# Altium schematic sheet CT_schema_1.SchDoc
size 539 x 541 mm
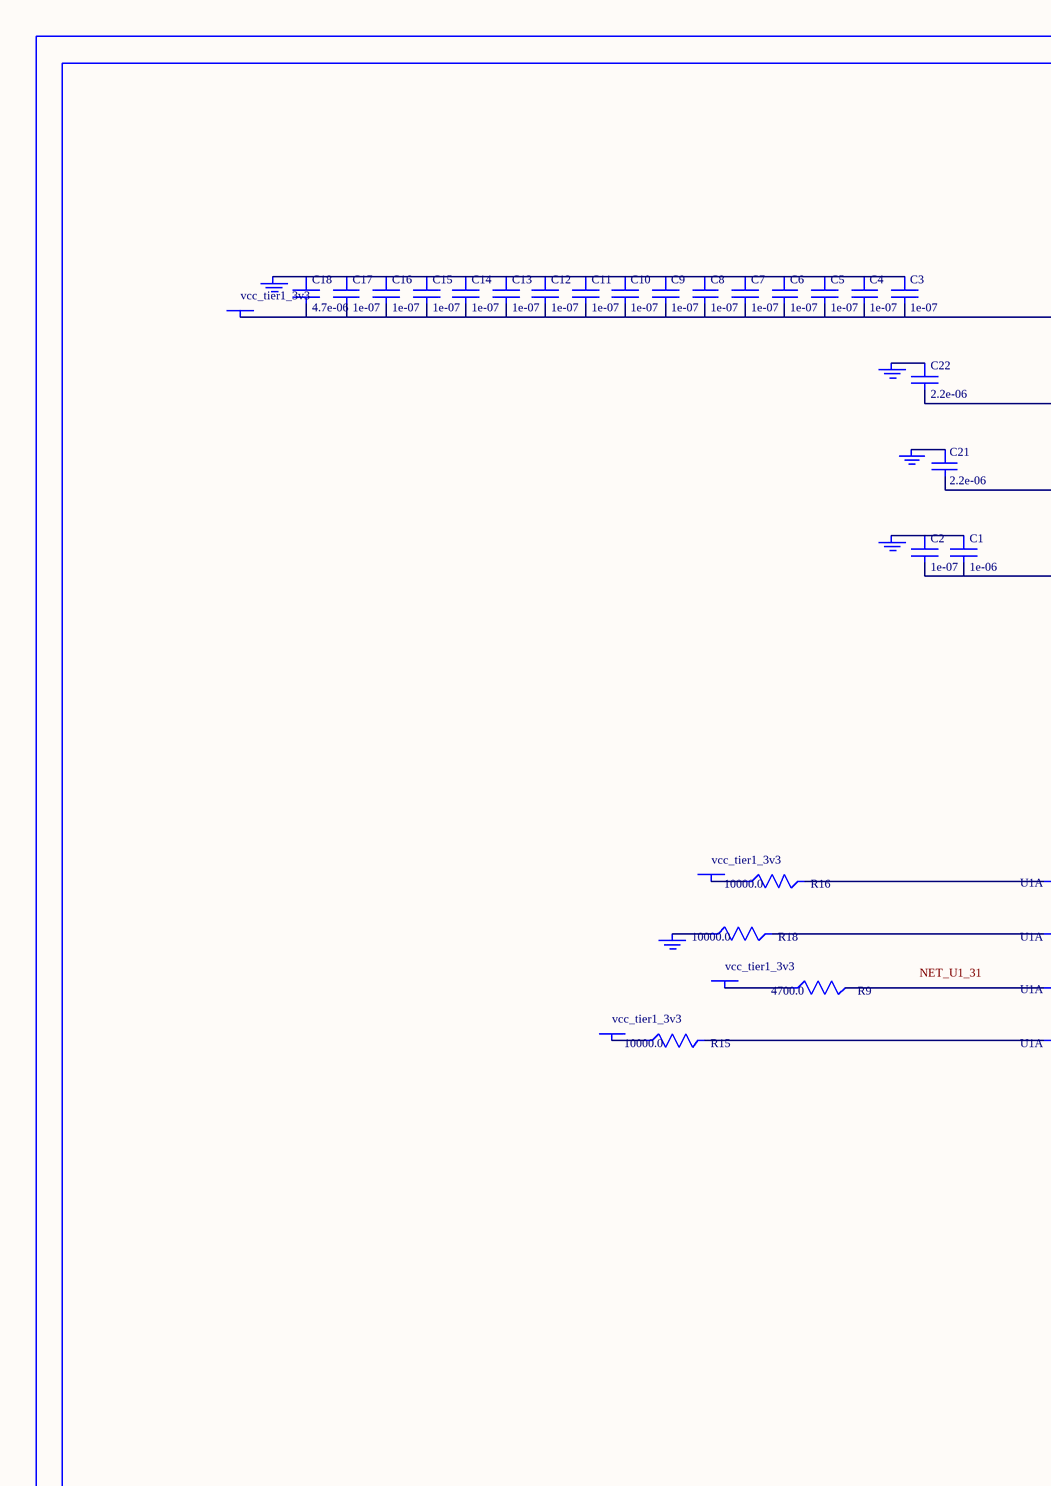
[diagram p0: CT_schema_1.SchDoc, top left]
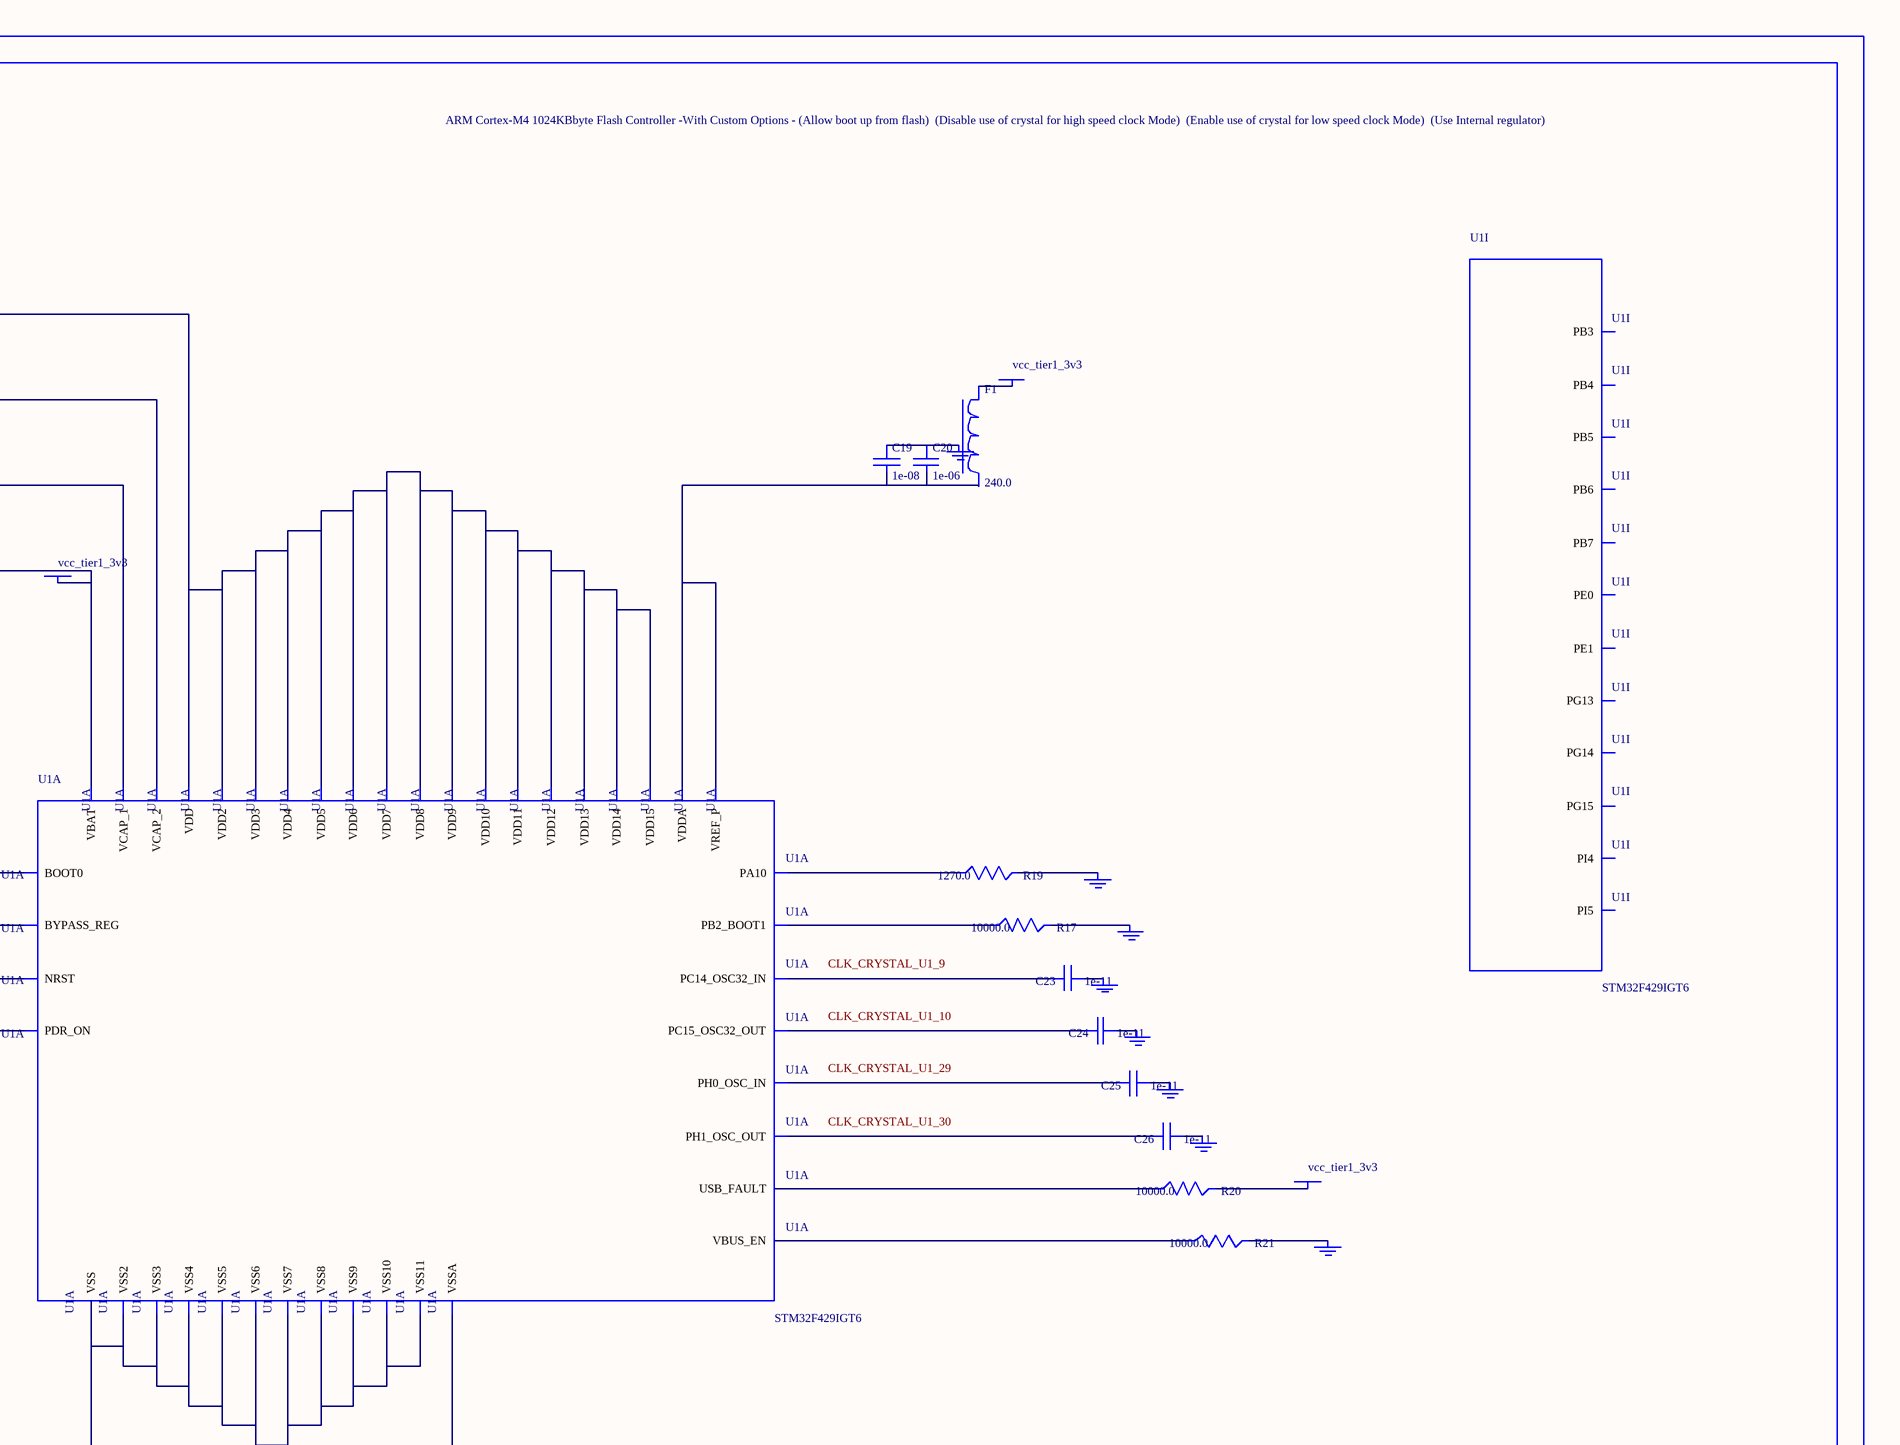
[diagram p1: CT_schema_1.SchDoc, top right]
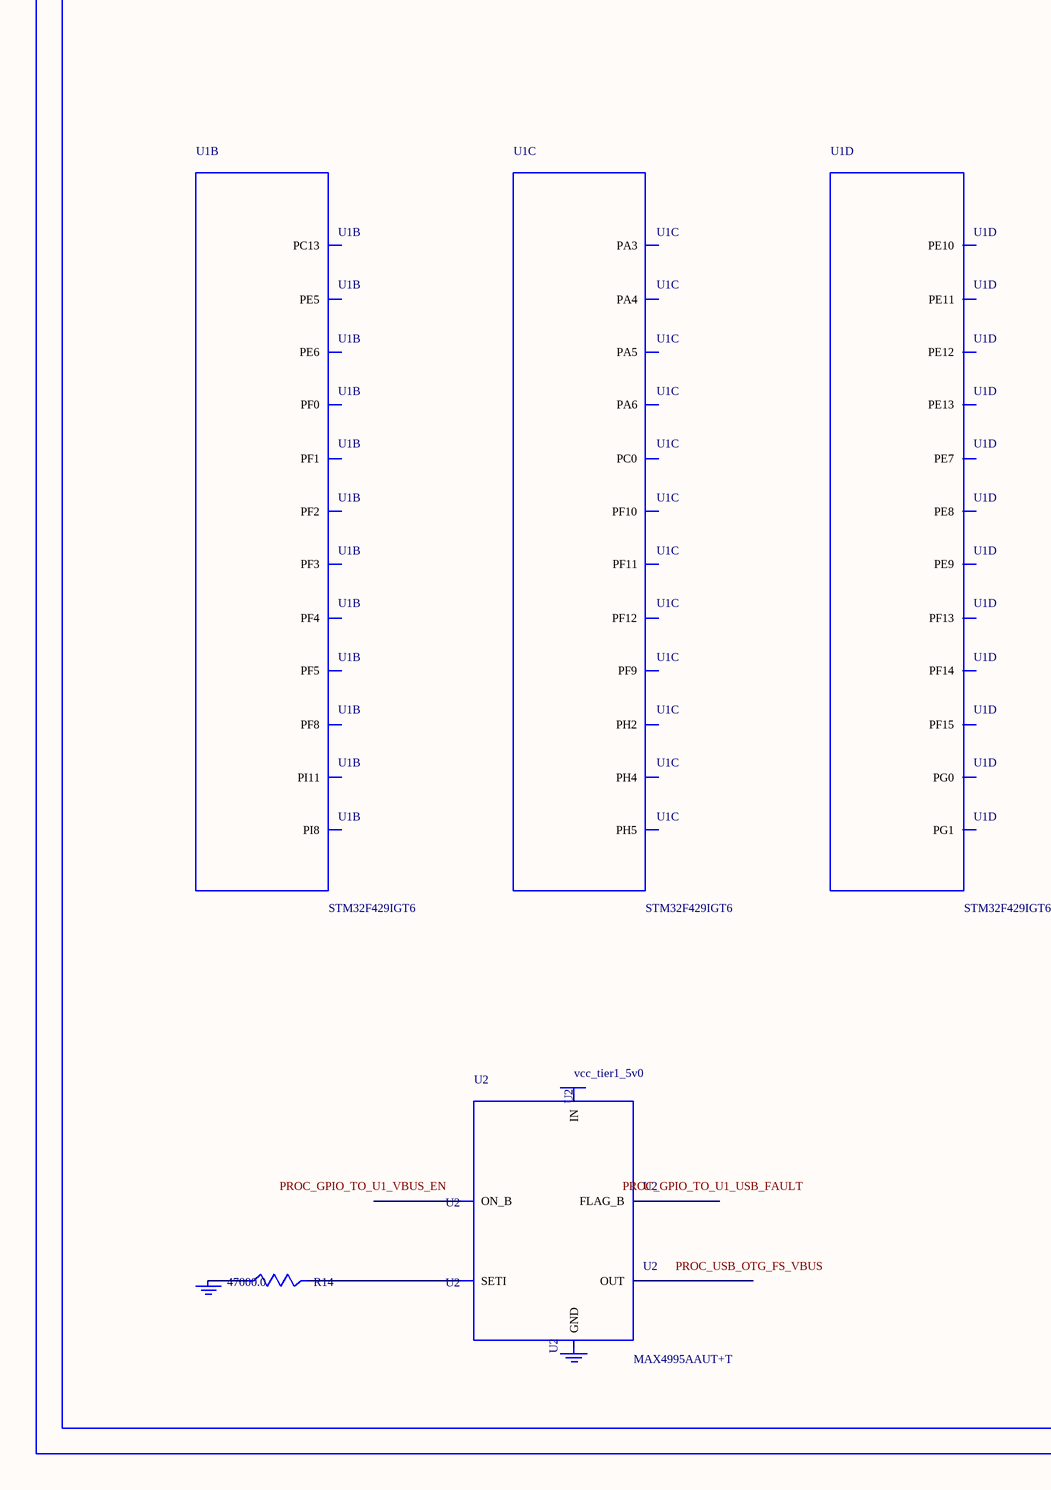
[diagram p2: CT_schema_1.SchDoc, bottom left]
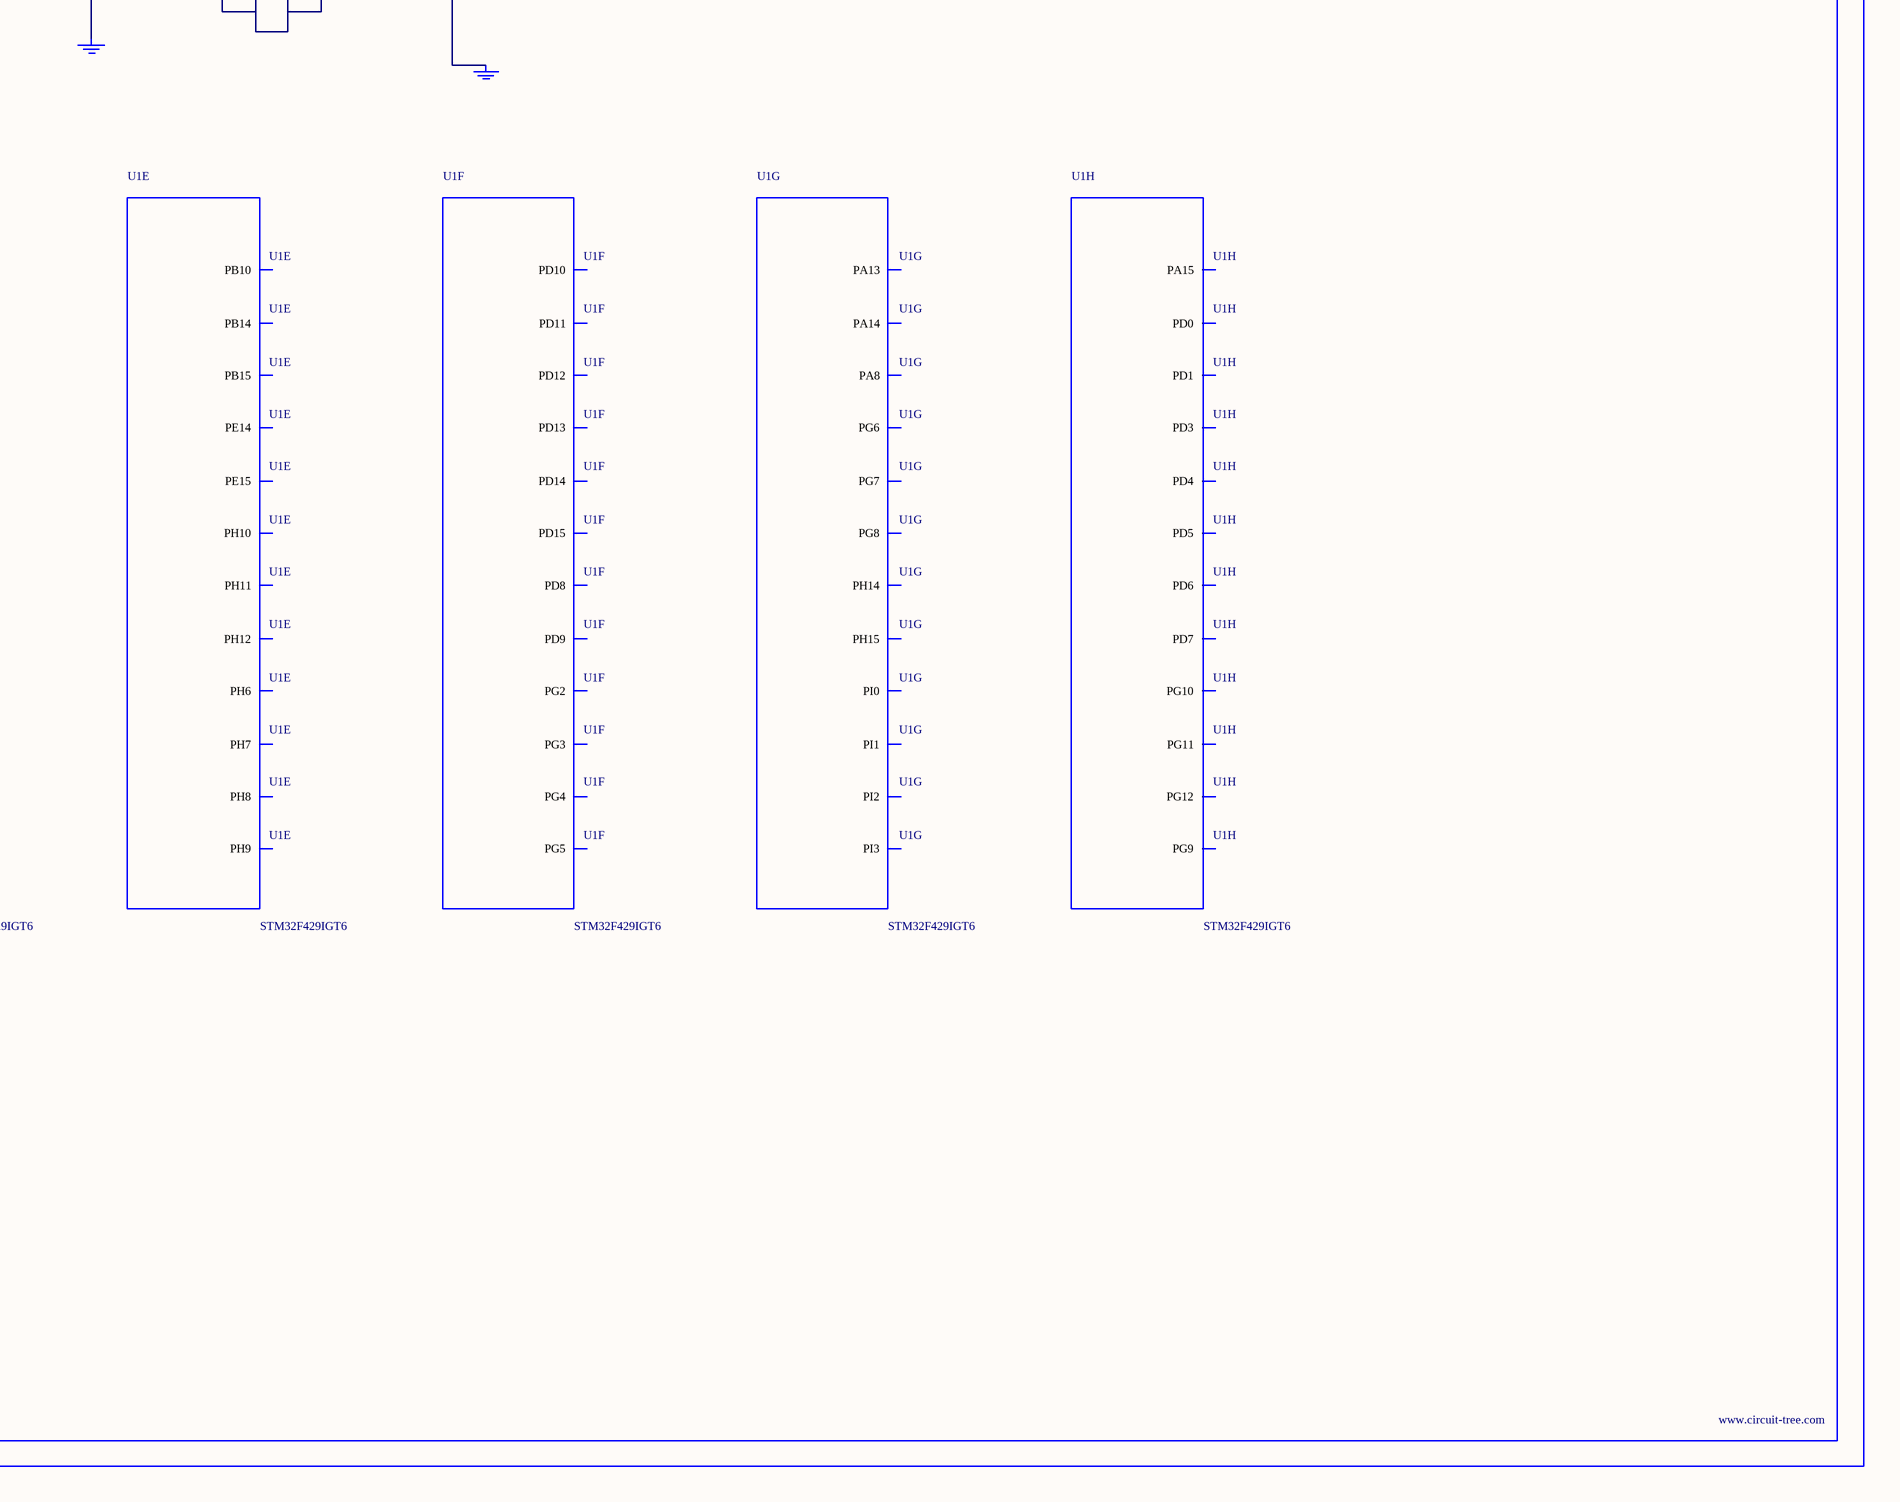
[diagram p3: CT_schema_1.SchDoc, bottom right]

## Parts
BORDER0  (no value)
C1  1e-06  [C0603]
C2  1e-07  [C0603]
C3  1e-07  [C0603]
C4  1e-07  [C0603]
C5  1e-07  [C0603]
C6  1e-07  [C0603]
C7  1e-07  [C0603]
C8  1e-07  [C0603]
C9  1e-07  [C0603]
C10  1e-07  [C0603]
C11  1e-07  [C0603]
C12  1e-07  [C0603]
C13  1e-07  [C0603]
C14  1e-07  [C0603]
C15  1e-07  [C0603]
C16  1e-07  [C0603]
C17  1e-07  [C0603]
C18  4.7e-06  [C0603]
C19  1e-08  [C0603]
C20  1e-06  [C0603]
C21  2.2e-06  [C0603]
C22  2.2e-06  [C0603]
C23  1e-11  [C0402]
C24  1e-11  [C0402]
C25  1e-11  [C0402]
C26  1e-11  [C0402]
F1  240.0  [L0603]
GND_INSTANCE_0_0  (no value)
GND_INSTANCE_0_1  (no value)
GND_INSTANCE_0_2  (no value)
GND_INSTANCE_0_3  (no value)
GND_INSTANCE_0_4  (no value)
GND_INSTANCE_0_5  (no value)
GND_INSTANCE_0_6  (no value)
GND_INSTANCE_0_7  (no value)
GND_INSTANCE_0_8  (no value)
GND_INSTANCE_0_9  (no value)
GND_INSTANCE_0_10  (no value)
GND_INSTANCE_0_11  (no value)
GND_INSTANCE_0_12  (no value)
GND_INSTANCE_0_13  (no value)
GND_INSTANCE_0_14  (no value)
GND_INSTANCE_0_15  (no value)
GND_INSTANCE_0_16  (no value)
POWER_INSTANCE_0_0  vcc_tier1_3v3
POWER_INSTANCE_0_1  vcc_tier1_3v3
POWER_INSTANCE_0_2  vcc_tier1_3v3
POWER_INSTANCE_0_3  vcc_tier1_3v3
POWER_INSTANCE_0_4  vcc_tier1_3v3
POWER_INSTANCE_0_5  vcc_tier1_3v3
POWER_INSTANCE_0_6  vcc_tier1_3v3
POWER_INSTANCE_0_7  vcc_tier1_5v0
R9  4700.0  [R0603]
R14  47000.0  [R0603]
R15  10000.0  [R0603]
R16  10000.0  [R0603]
R17  10000.0  [R0603]
R18  10000.0  [R0603]
R19  1270.0  [R0603]
R20  10000.0  [R0603]
R21  10000.0  [R0603]
U1  STM32F429IGT6  [LQFP176]  (parts A,B,C,D,E,F,G,H,I of 15)
U2  MAX4995AAUT+T  [SOT-23-6]

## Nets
NetC1_1: C1.1 C2.1 GND_INSTANCE_0_1.0(GND)
NetC1_2: C1.2 C2.2 POWER_INSTANCE_0_1.0(PWR) U1.6(VBAT)
NetC3_1: C3.1 C4.1 C5.1 C6.1 C7.1 C8.1 C9.1 C10.1 C11.1 C12.1 C13.1 C14.1 C15.1 C16.1 C17.1 C18.1 GND_INSTANCE_0_4.0(GND)
NetC3_2: C3.2 C4.2 C5.2 C6.2 C7.2 C8.2 C9.2 C10.2 C11.2 C12.2 C13.2 C14.2 C15.2 C16.2 C17.2 C18.2 POWER_INSTANCE_0_2.0(PWR) U1.15(VDD) U1.23(VDD2) U1.36(VDD3) U1.49(VDD4) U1.62(VDD5) U1.72(VDD6) U1.82(VDD7) U1.91(VDD8) U1.103(VDD9) U1.114(VDD10) U1.127(VDD11) U1.136(VDD12) U1.149(VDD13) U1.159(VDD14) U1.172(VDD15)
NetC19_1: C19.1 C20.1 GND_INSTANCE_0_8.0(GND)
NetC19_2: C19.2 C20.2 U1.38(VREF_P) U1.39(VDDA)
NetC21_1: C21.1 GND_INSTANCE_0_11.0(GND)
NetC21_2: C21.2 U1.81(VCAP_1)
NetC22_1: C22.1 GND_INSTANCE_0_13.0(GND)
NetC22_2: C22.2 U1.125(VCAP_2)
NetC23_1: C23.1 GND_INSTANCE_0_2.0(GND)
NetC23_2: C23.2 U1.9(PC14_OSC32_IN)
NetC24_1: C24.1 GND_INSTANCE_0_3.0(GND)
NetC24_2: C24.2 U1.10(PC15_OSC32_OUT)
NetC25_1: C25.1 GND_INSTANCE_0_5.0(GND)
NetC25_2: C25.2 U1.29(PH0_OSC_IN)
NetC26_1: C26.1 GND_INSTANCE_0_6.0(GND)
NetC26_2: C26.2 U1.30(PH1_OSC_OUT)
NetF1_1: F1.1 POWER_INSTANCE_0_3.0(PWR)
NetGND_INSTANCE_0_0_0: GND_INSTANCE_0_0.0(GND) R21.2
NetGND_INSTANCE_0_7_0: GND_INSTANCE_0_7.0(GND) U1.37(VSSA)
NetGND_INSTANCE_0_9_0: GND_INSTANCE_0_9.0(GND) R18.1
NetGND_INSTANCE_0_10_0: GND_INSTANCE_0_10.0(GND) R17.2
NetGND_INSTANCE_0_12_0: GND_INSTANCE_0_12.0(GND) R19.2
NetGND_INSTANCE_0_14_0: GND_INSTANCE_0_14.0(GND) U1.14(VSS) U1.22(VSS2) U1.61(VSS3) U1.71(VSS4) U1.90(VSS5) U1.102(VSS6) U1.113(VSS7) U1.126(VSS8) U1.135(VSS9) U1.148(VSS10) U1.158(VSS11)
NetGND_INSTANCE_0_15_0: GND_INSTANCE_0_15.0(GND) R14.1
NetPOWER_INSTANCE_0_0_0: POWER_INSTANCE_0_0.0(PWR) R20.2
NetPOWER_INSTANCE_0_4_0: POWER_INSTANCE_0_4.0(PWR) R16.1
NetPOWER_INSTANCE_0_5_0: POWER_INSTANCE_0_5.0(PWR) R15.1
NetPOWER_INSTANCE_0_6_0: POWER_INSTANCE_0_6.0(PWR) R9.1
NetR9_2: R9.2 U1.31(NRST)
NetR14_2: R14.2 U2.3(SETI)
NetR15_2: R15.2 U1.171(PDR_ON)
NetR16_2: R16.2 U1.166(BOOT0)
NetR17_1: R17.1 U1.58(PB2_BOOT1)
NetR18_2: R18.2 U1.48(BYPASS_REG)
NetR19_1: R19.1 U1.121(PA10)
NetR20_1: R20.1 U1.3(USB_FAULT)
NetR21_1: R21.1 U1.2(VBUS_EN)

Not connected (* = marked no-connect by the designer): F1 2; GND_INSTANCE_0_16 0(GND); POWER_INSTANCE_0_7 0(PWR); U1 4(PE5) 5(PE6) 7(PI8) 8(PC13) 13(PI11) 16(PF0) 17(PF1) 18(PF2) 19(PF3) 20(PF4) 21(PF5) 26(PF8) 27(PF9) 28(PF10) 32(PC0) 43(PH2) 45(PH4) 46(PH5) 47(PA3) 50(PA4) 51(PA5) 52(PA6) 59(PF11) 60(PF12) 63(PF13) 64(PF14) 65(PF15) 66(PG0) 67(PG1) 68(PE7) 69(PE8) 70(PE9) 73(PE10) 74(PE11) 75(PE12) 76(PE13) 77(PE14) 78(PE15) 79(PB10) 83(PH6) 84(PH7) 85(PH8) 86(PH9) 87(PH10) 88(PH11) 89(PH12) 94(PB14) 95(PB15) 96(PD8) 97(PD9) 98(PD10) 99(PD11) 100(PD12) 101(PD13) 104(PD14) 105(PD15) 106(PG2) 107(PG3) 108(PG4) 109(PG5) 110(PG6) 111(PG7) 112(PG8) 119(PA8) 124(PA13) 129(PH14) 130(PH15) 131(PI0) 132(PI1) 133(PI2) 134(PI3) 137(PA14) 138(PA15) 142(PD0) 143(PD1) 145(PD3) 146(PD4) 147(PD5) 150(PD6) 151(PD7) 152(PG9) 153(PG10) 154(PG11) 155(PG12) 156(PG13) 157(PG14) 160(PG15) 161(PB3) 162(PB4) 163(PB5) 164(PB6) 165(PB7) 169(PE0) 170(PE1) 173(PI4) 174(PI5); U2 1(OUT) 2(GND) 4(ON_B) 5(IN) 6(FLAG_B)

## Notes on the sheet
- Labels drawn without touching a wire or pin: CLK_CRYSTAL_U1_9, CLK_CRYSTAL_U1_10, CLK_CRYSTAL_U1_29, CLK_CRYSTAL_U1_30, NET_U1_31, PROC_GPIO_TO_U1_USB_FAULT, PROC_GPIO_TO_U1_VBUS_EN, PROC_USB_OTG_FS_VBUS

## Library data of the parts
BORDER0 = BORDER_PAGE0
C1 C20 = C0603C105K3RACTU
C2-C17 = 06035C104K4Z2A
C18 = GRM188R6YA475KE15D
C19 = 06035C103K4Z2A
C21 C22 = C0603C225K8RACTU
C23-C26 = C0402C100K3GACTU
F1 = Z0603C241ASMST
GND_INSTANCE_0_0-GND_INSTANCE_0_16 = GND
POWER_INSTANCE_0_0-POWER_INSTANCE_0_7 = PWR
R9 = RC0603JR-074K7L
R14 = RC0603JR-0747KL
R15-R18 R20 R21 = RC0603JR-0710KL
R19 = RC0603FR-071K27L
